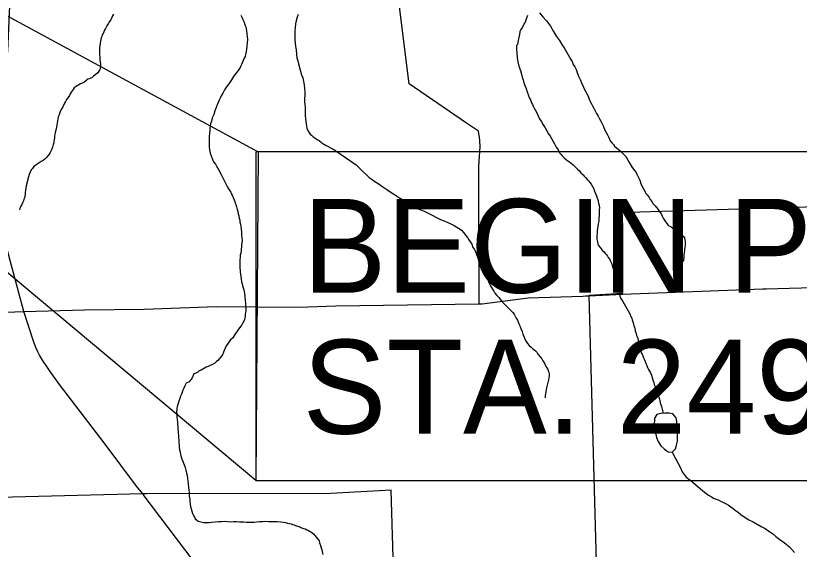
# Model space of a CAD drawing. Extents: x 0 to 44.3, y 0 to 22.
# Drawn here: x 6.296 to 7.465, y 15.453 to 16.249 of the extents above; entities that cross this region are included whole.
import ezdxf

# ---------------------------------------------------------------- set-up
doc = ezdxf.new("R2010")
doc.units = 0
for name, color, linetype in [('GM_X_City_Street', 7, 'Continuous'), ('GM_X_Corporation', 7, 'Continuous'), ('GM_X_County_Road', 7, 'Continuous'), ('GM_X_Minor_Lake', 7, 'Continuous'), ('GM_X_Minor_River', 7, 'Continuous'), ('SH_Text', 7, 'Continuous')]:
    doc.layers.add(name, color=color, linetype=linetype)

msp = doc.modelspace()

# ---------------------------------------------------------------- linework, layer by layer
at = {"layer": 'GM_X_City_Street'}
for points in [[(6.3085, 15.8078), (6.2524, 16.0154), (6.2644, 16.0723), (6.2847, 16.1957), (6.2898, 16.3085), (6.2909, 16.383), (6.3097, 16.5007), (6.3117, 16.6181), (6.3141, 16.71), (6.3024, 16.8069)], [(6.9874, 15.819), (6.9868, 16.0243), (6.9888, 16.0536), (6.9882, 16.062), (6.9879, 16.0675), (6.9871, 16.0729), (6.9862, 16.0764), (6.9684, 16.0883), (6.8829, 16.1469), (6.8664, 16.2823)]]:
    msp.add_lwpolyline(points, dxfattribs=at)
at = {"layer": 'GM_X_Corporation'}
for points in [[(7.7377, 15.9714), (7.1944, 15.955), (7.2008, 15.8343), (7.1511, 15.8316), (7.1669, 15.2531)], [(7.7377, 15.9714), (7.1944, 15.955), (7.2008, 15.8343), (7.1511, 15.8316), (7.1669, 15.2531)], [(6.8649, 15.2563), (6.8561, 15.5411), (6.7665, 15.5364), (6.4917, 15.5358), (6.4859, 15.5358), (6.1744, 15.5281), (6.1773, 15.2593)], [(6.8649, 15.2563), (6.8561, 15.5411), (6.7665, 15.5364), (6.4917, 15.5358), (6.4859, 15.5358), (6.1744, 15.5281), (6.1773, 15.2593)]]:
    msp.add_lwpolyline(points, dxfattribs=at)
at = {"layer": 'GM_X_County_Road'}
for points in [[(7.4152, 15.8417), (7.573, 15.8459), (7.9476, 15.8561), (8.0638, 15.86)], [(7.1459, 15.8309), (7.1509, 15.831), (7.2011, 15.8337), (7.4102, 15.8416), (7.4152, 15.8417)], [(5.4899, 15.7322), (5.7174, 15.7377), (5.884, 15.7402), (5.9198, 15.7511), (5.972, 15.7734), (6.0144, 15.7954), (6.0165, 15.7955), (6.0769, 15.7966), (6.0809, 15.7969), (6.2401, 15.8054), (6.3085, 15.8078), (6.399, 15.8104), (6.4879, 15.8111), (6.5954, 15.815), (6.7181, 15.8144), (6.7739, 15.816), (6.9874, 15.819), (6.992, 15.8191), (7.0603, 15.8282), (7.1419, 15.8307), (7.1459, 15.8309)], [(6.4858, 15.5357), (6.4766, 15.5475), (6.4298, 15.6097), (6.3617, 15.6991), (6.3476, 15.7181), (6.3426, 15.7258), (6.3365, 15.7352), (6.3319, 15.7426), (6.3292, 15.7476), (6.3266, 15.7539), (6.3231, 15.7637), (6.3085, 15.8078)], [(6.7741, 15.1514), (6.7729, 15.1531), (6.6991, 15.2503), (6.6354, 15.3379), (6.4864, 15.5349), (6.4858, 15.5357)]]:
    msp.add_lwpolyline(points, dxfattribs=at)
at = {"layer": 'GM_X_Minor_Lake'}
for points in [[(7.2833, 15.6248), (7.2833, 15.6314), (7.2824, 15.6435), (7.2813, 15.6492), (7.2763, 15.6552), (7.2706, 15.6563), (7.2642, 15.6559), (7.2581, 15.6555), (7.2525, 15.654), (7.2487, 15.6486), (7.2485, 15.6371)], [(7.2485, 15.6371), (7.2492, 15.6319), (7.2504, 15.6263), (7.2519, 15.6198), (7.2542, 15.6138), (7.2584, 15.6073), (7.2637, 15.6024), (7.2694, 15.5987), (7.2751, 15.5979)], [(7.2751, 15.5979), (7.2804, 15.6029), (7.2819, 15.6082), (7.283, 15.6143), (7.2833, 15.6204), (7.2833, 15.6248)]]:
    msp.add_lwpolyline(points, dxfattribs=at)
at = {"layer": 'GM_X_Minor_River'}
for points in [[(6.4424, 16.2511), (6.4409, 16.2484), (6.4395, 16.2458), (6.438, 16.2427), (6.4362, 16.24), (6.4343, 16.2365), (6.4325, 16.2335), (6.4303, 16.2296), (6.4288, 16.2269), (6.4277, 16.2247), (6.4266, 16.2223), (6.4255, 16.2201), (6.4248, 16.2178), (6.4237, 16.2155), (6.4234, 16.2132), (6.4227, 16.2105), (6.4223, 16.2078), (6.4216, 16.2044), (6.4213, 16.201), (6.4214, 16.1979), (6.4211, 16.1957), (6.4211, 16.193), (6.4211, 16.1907), (6.4216, 16.1869), (6.422, 16.1831), (6.4225, 16.1794), (6.4226, 16.1759), (6.4226, 16.1733), (6.4223, 16.1706), (6.4216, 16.1687), (6.419, 16.1637), (6.4168, 16.1622), (6.4126, 16.1587), (6.4097, 16.1563), (6.4059, 16.1547), (6.404, 16.1539), (6.4006, 16.1512), (6.398, 16.1493), (6.3946, 16.1477), (6.3928, 16.1469), (6.3867, 16.1434), (6.3837, 16.1414), (6.3819, 16.1387), (6.3808, 16.1368), (6.3793, 16.1345), (6.3778, 16.1322), (6.3764, 16.1295), (6.3742, 16.1264), (6.3723, 16.1237), (6.3705, 16.121), (6.369, 16.1184), (6.3668, 16.113), (6.3642, 16.1088), (6.3624, 16.1046), (6.361, 16.1011), (6.3599, 16.0977), (6.3592, 16.095), (6.3585, 16.092), (6.3582, 16.0889), (6.3575, 16.0859), (6.3572, 16.0824), (6.3561, 16.0779), (6.3554, 16.0748), (6.3547, 16.0714), (6.3544, 16.0695), (6.3544, 16.0672), (6.3537, 16.0638), (6.3534, 16.0619), (6.353, 16.0592), (6.3523, 16.0565), (6.3513, 16.0527), (6.3498, 16.0485), (6.3476, 16.045), (6.3461, 16.0424), (6.3443, 16.0397), (6.3421, 16.0373), (6.3398, 16.035), (6.3372, 16.0327), (6.3342, 16.0311), (6.3312, 16.0292), (6.3286, 16.0276), (6.326, 16.0256), (6.3233, 16.0237), (6.3215, 16.021), (6.3196, 16.0187), (6.3178, 16.0152), (6.3167, 16.0122), (6.3153, 16.0087), (6.3121, 15.995)], [(6.6322, 16.2497), (6.6338, 16.2463), (6.635, 16.2429), (6.6365, 16.2399), (6.6377, 16.2369), (6.6385, 16.2342), (6.6394, 16.232), (6.6402, 16.2293), (6.6406, 16.2263), (6.6411, 16.2218), (6.6415, 16.2176), (6.642, 16.213), (6.6413, 16.2081), (6.641, 16.2035), (6.6404, 16.1989), (6.64, 16.1951), (6.639, 16.1909), (6.6383, 16.1879), (6.6368, 16.1852), (6.6332, 16.176), (6.6321, 16.1741), (6.631, 16.1714), (6.6292, 16.1684), (6.6266, 16.1649), (6.6236, 16.1614), (6.621, 16.158), (6.6181, 16.153), (6.614, 16.1472), (6.6107, 16.1426), (6.6077, 16.138), (6.6052, 16.133), (6.6026, 16.1291), (6.6011, 16.1257), (6.5997, 16.1226), (6.5982, 16.1192), (6.5968, 16.1157), (6.5953, 16.1119), (6.5935, 16.1069), (6.5917, 16.1012), (6.5895, 16.0962), (6.5881, 16.0913), (6.587, 16.0874), (6.586, 16.0817), (6.5857, 16.0772), (6.5854, 16.0734), (6.5847, 16.0684), (6.5848, 16.0635), (6.5849, 16.0589), (6.585, 16.0536), (6.5855, 16.0483), (6.5863, 16.0437), (6.5876, 16.0396), (6.5895, 16.0358), (6.5915, 16.0309), (6.5943, 16.0272), (6.5962, 16.0234), (6.5986, 16.0193), (6.6029, 16.0122), (6.6068, 16.0042), (6.6088, 16.0001), (6.6124, 15.993), (6.6135, 15.9907), (6.6155, 15.9877), (6.617, 15.9854), (6.6178, 15.9836), (6.619, 15.9809)], [(6.7176, 16.2505), (6.7161, 16.2463), (6.7147, 16.241), (6.7137, 16.2364), (6.713, 16.2311), (6.7127, 16.2261), (6.7124, 16.2219), (6.7125, 16.2174), (6.7126, 16.2128), (6.713, 16.2083), (6.7135, 16.2026), (6.7144, 16.1977), (6.7149, 16.1916), (6.7157, 16.1859), (6.717, 16.1814), (6.7182, 16.1768), (6.7194, 16.1715), (6.7211, 16.1659), (6.7227, 16.1606), (6.7243, 16.1561), (6.7255, 16.1508), (6.7264, 16.1458), (6.7272, 16.1398), (6.7273, 16.1356), (6.7274, 16.1318), (6.7272, 16.1235), (6.7272, 16.1197), (6.7273, 16.1162), (6.7278, 16.1124), (6.7278, 16.1083), (6.7279, 16.1045), (6.728, 16.1003), (6.7285, 16.0946), (6.7298, 16.084), (6.7306, 16.081), (6.7318, 16.0776), (6.7334, 16.0749), (6.7353, 16.0723), (6.7376, 16.0705), (6.74, 16.0682), (6.7423, 16.0664), (6.7446, 16.0653), (6.7469, 16.0638), (6.7488, 16.0627), (6.7523, 16.0597), (6.755, 16.0575), (6.7722, 16.0483), (6.7569, 16.0564), (6.7573, 16.0564)], [(7.0593, 16.2492), (7.0579, 16.245), (7.0572, 16.2423), (7.0561, 16.2392), (7.0546, 16.2369), (7.052, 16.2316), (7.0498, 16.2281), (7.0483, 16.2251), (7.0476, 16.2209), (7.0462, 16.2144), (7.0445, 16.206), (7.043, 16.2041), (7.0431, 16.1995), (7.0435, 16.1934), (7.044, 16.1858), (7.0449, 16.1801), (7.0465, 16.1737), (7.0489, 16.1669), (7.0505, 16.1616), (7.0517, 16.157), (7.0529, 16.1533), (7.0542, 16.1487), (7.0561, 16.1438), (7.0573, 16.14), (7.0589, 16.1351), (7.0605, 16.1313), (7.0617, 16.1283), (7.0629, 16.1249), (7.0645, 16.1222), (7.0657, 16.1188), (7.0672, 16.1162), (7.068, 16.1139), (7.0692, 16.1117), (7.0708, 16.1083), (7.0731, 16.1049), (7.0751, 16.1003), (7.0774, 16.0951), (7.0806, 16.0905), (7.0829, 16.086), (7.0857, 16.0815), (7.0884, 16.077), (7.0907, 16.0728), (7.0931, 16.0691), (7.0997, 16.0577), (7.1009, 16.0555), (7.1025, 16.0528), (7.104, 16.0502), (7.1056, 16.0476), (7.1072, 16.0445), (7.1095, 16.0419), (7.1114, 16.0397), (7.1141, 16.037), (7.1176, 16.0337), (7.121, 16.0314), (7.1241, 16.0292), (7.1276, 16.0262), (7.1307, 16.0232), (7.1342, 16.0198), (7.1369, 16.0172)], [(7.0775, 16.2529), (7.0825, 16.2472), (7.0876, 16.2412), (7.0938, 16.233), (7.0981, 16.2254), (7.1028, 16.2179), (7.1071, 16.2115), (7.1106, 16.2058), (7.1141, 16.2006), (7.1219, 16.187), (7.1243, 16.1832), (7.1262, 16.1802), (7.1278, 16.176), (7.1301, 16.1723), (7.1321, 16.1685), (7.1337, 16.164), (7.1357, 16.1587), (7.138, 16.1534), (7.1404, 16.1477), (7.1428, 16.1424), (7.1447, 16.1386), (7.1463, 16.1352), (7.1479, 16.1322), (7.1499, 16.1285), (7.1522, 16.1228), (7.1546, 16.1183), (7.1565, 16.1145), (7.1585, 16.1107), (7.1605, 16.1069), (7.1624, 16.1028), (7.1648, 16.099), (7.1671, 16.0952), (7.1691, 16.0915), (7.171, 16.0877), (7.173, 16.0835), (7.1746, 16.0782), (7.177, 16.0745), (7.1789, 16.0711), (7.1809, 16.0669), (7.1829, 16.0624), (7.1852, 16.059), (7.1875, 16.0568), (7.1894, 16.0541), (7.1921, 16.0519), (7.1945, 16.0496), (7.1975, 16.0474), (7.2006, 16.0444), (7.206, 16.0388), (7.2107, 16.0309), (7.2158, 16.0226), (7.2197, 16.0173), (7.2216, 16.0147), (7.2224, 16.0124), (7.224, 16.0094), (7.2248, 16.0075), (7.2268, 16.0033), (7.2287, 15.998), (7.2366, 15.9833), (7.2381, 15.9815), (7.2409, 15.9777), (7.2424, 15.9747), (7.2448, 15.9717), (7.2471, 15.9683), (7.2498, 15.9653), (7.2521, 15.9626), (7.2544, 15.96), (7.256, 15.9574), (7.2576, 15.9547), (7.2591, 15.9521), (7.2603, 15.9498), (7.2619, 15.9468), (7.2638, 15.9438), (7.2654, 15.9412), (7.2677, 15.9382), (7.2693, 15.9359), (7.2716, 15.9348), (7.2739, 15.9337), (7.277, 15.9315), (7.2789, 15.9303), (7.2812, 15.9289), (7.2831, 15.9277), (7.2854, 15.9255), (7.2873, 15.9236), (7.2896, 15.9221), (7.2916, 15.9199), (7.2935, 15.9173), (7.2943, 15.9142), (7.2948, 15.9119), (7.2948, 15.907), (7.2941, 15.9032), (7.2938, 15.9005), (7.2935, 15.8986), (7.2931, 15.8959), (7.2928, 15.8921), (7.2925, 15.8876), (7.2918, 15.8822)], [(6.7722, 16.0483), (6.8039, 16.0264), (6.8093, 16.0211), (6.8143, 16.0159), (6.8193, 16.0114), (6.8235, 16.0077), (6.8278, 16.0047), (6.832, 16.0017), (6.837, 15.9983), (6.8439, 15.9935), (6.8497, 15.9894), (6.8562, 15.9853), (6.8627, 15.9809), (6.8685, 15.9771), (6.8842, 15.9682), (6.8881, 15.9656), (6.8915, 15.9638), (6.8942, 15.9623), (6.8977, 15.9605), (6.9022, 15.9586), (6.9065, 15.9568), (6.9114, 15.9542), (6.9172, 15.9512), (6.9237, 15.9479), (6.9298, 15.945), (6.936, 15.9424), (6.9405, 15.9406), (6.9444, 15.9391), (6.9474, 15.9372), (6.9501, 15.9358), (6.954, 15.9335), (6.9566, 15.932), (6.9589, 15.9306), (6.9612, 15.9291), (6.9647, 15.9249), (6.9671, 15.9216), (6.9698, 15.9182), (6.9721, 15.9148), (6.9741, 15.9114), (6.9764, 15.908), (6.9776, 15.9042), (6.9799, 15.9008), (6.9819, 15.8971), (6.9835, 15.8929), (6.9851, 15.8887), (6.9871, 15.8842), (6.989, 15.8789), (6.9918, 15.8736), (6.9945, 15.8687), (6.9973, 15.8642), (6.9992, 15.8593), (7.0005, 15.8551), (7.002, 15.851), (7.0032, 15.8483), (7.0044, 15.8461), (7.0056, 15.8434), (7.0071, 15.8411), (7.0091, 15.8381), (7.011, 15.8351), (7.0138, 15.8317), (7.0169, 15.8284), (7.0203, 15.8242), (7.0242, 15.8197), (7.0354, 15.8089), (7.0377, 15.8062), (7.0397, 15.8036), (7.0413, 15.8006), (7.0428, 15.7976), (7.0444, 15.7949), (7.0456, 15.7923), (7.0468, 15.7893), (7.0483, 15.7862), (7.0495, 15.7825), (7.0515, 15.7779), (7.0527, 15.7738), (7.0547, 15.7692), (7.0567, 15.7643), (7.0594, 15.7602), (7.0621, 15.7572), (7.0648, 15.7545), (7.0671, 15.7527), (7.069, 15.7512), (7.0713, 15.7493), (7.0733, 15.7471), (7.0756, 15.7437), (7.0783, 15.7403), (7.0807, 15.7373), (7.0826, 15.7343), (7.0842, 15.7316), (7.0858, 15.7282), (7.0869, 15.7256), (7.0885, 15.7237), (7.09, 15.7211), (7.0905, 15.7192), (7.0913, 15.7173), (7.0917, 15.7142)], [(7.1369, 16.0172), (7.1392, 16.0146), (7.1423, 16.0116), (7.1442, 16.0097), (7.1461, 16.0075), (7.1492, 16.0041), (7.1508, 16.0018), (7.1527, 16), (7.1543, 15.9977), (7.1566, 15.9943), (7.1582, 15.9905), (7.1594, 15.9871), (7.161, 15.9834), (7.1622, 15.98), (7.1634, 15.9769), (7.1642, 15.9747), (7.165, 15.972), (7.1654, 15.9686), (7.1662, 15.9663), (7.1667, 15.9618), (7.1663, 15.9599), (7.1664, 15.9561), (7.1664, 15.9519), (7.1661, 15.9465), (7.1658, 15.9424), (7.1651, 15.9382), (7.1644, 15.9347), (7.1637, 15.9309), (7.1634, 15.9279), (7.1628, 15.918), (7.1628, 15.9157), (7.1637, 15.9115), (7.1645, 15.9081), (7.1653, 15.9062), (7.1672, 15.9036), (7.1699, 15.9006), (7.1715, 15.8983), (7.1738, 15.8965), (7.1754, 15.8942), (7.1773, 15.8923), (7.1788, 15.8901), (7.18, 15.8882), (7.1823, 15.8852), (7.1835, 15.8829), (7.1843, 15.881), (7.1851, 15.8788), (7.1863, 15.8742), (7.1871, 15.8719), (7.1883, 15.8682), (7.1899, 15.864), (7.1916, 15.8564), (7.1944, 15.8454), (7.1964, 15.8413), (7.1964, 15.8375), (7.1965, 15.8356), (7.1965, 15.8329), (7.1977, 15.8284), (7.1997, 15.8257), (7.2016, 15.8227), (7.2036, 15.819), (7.2114, 15.805), (7.2126, 15.8027), (7.2134, 15.8008), (7.2149, 15.7974), (7.2154, 15.7952), (7.2165, 15.7921), (7.2174, 15.7895), (7.2182, 15.7865), (7.2194, 15.7831), (7.2202, 15.7789), (7.2214, 15.7751), (7.2222, 15.7721), (7.223, 15.7698), (7.2238, 15.7675), (7.2246, 15.7649), (7.225, 15.7622), (7.2258, 15.7596), (7.2263, 15.7565), (7.2271, 15.7535), (7.2279, 15.7512), (7.2283, 15.7494), (7.2291, 15.7463), (7.2306, 15.7441), (7.2314, 15.7418), (7.2326, 15.7384), (7.2338, 15.7357), (7.235, 15.7331), (7.2362, 15.7301), (7.2374, 15.7274), (7.2386, 15.7244), (7.2398, 15.7214), (7.2413, 15.7187), (7.2429, 15.7161), (7.2445, 15.7127), (7.2456, 15.7093), (7.2465, 15.7059), (7.2477, 15.7021), (7.2485, 15.6987), (7.2497, 15.6957), (7.2505, 15.693), (7.2517, 15.69)], [(6.3121, 15.995), (6.3114, 15.9916), (6.3111, 15.9882), (6.3104, 15.9851), (6.3105, 15.9821), (6.3101, 15.9798), (6.3094, 15.9771), (6.3087, 15.9752), (6.308, 15.9725), (6.3065, 15.9695), (6.3051, 15.9664), (6.3036, 15.9637), (6.3025, 15.9614), (6.3022, 15.9591), (6.3018, 15.9591), (6.3022, 15.9591)], [(6.619, 15.9809), (6.6222, 15.9741), (6.623, 15.9719), (6.6238, 15.9692), (6.6246, 15.967), (6.6254, 15.9639), (6.6266, 15.9598), (6.6275, 15.9568), (6.6283, 15.9534), (6.6291, 15.9503), (6.6295, 15.9469), (6.6304, 15.9439), (6.6308, 15.9409), (6.6316, 15.9379), (6.632, 15.9344), (6.6325, 15.9307), (6.633, 15.9261), (6.633, 15.9223), (6.6335, 15.9174), (6.634, 15.9136), (6.6336, 15.9102), (6.6333, 15.9067), (6.633, 15.9037), (6.6327, 15.901), (6.6324, 15.898), (6.632, 15.8949), (6.6313, 15.8915), (6.631, 15.8881), (6.6307, 15.885), (6.6304, 15.8812), (6.6305, 15.8782), (6.6305, 15.8752), (6.6306, 15.8718), (6.631, 15.8691), (6.6311, 15.8664), (6.6315, 15.8634), (6.6319, 15.86), (6.6324, 15.8562), (6.6332, 15.852), (6.634, 15.849), (6.6348, 15.8464), (6.6357, 15.843), (6.6365, 15.84), (6.6369, 15.8377), (6.6373, 15.8347), (6.6378, 15.8312), (6.6382, 15.8282), (6.6387, 15.8252), (6.6387, 15.8229), (6.6391, 15.821), (6.6392, 15.8187), (6.6393, 15.8127), (6.6393, 15.8108), (6.6394, 15.8085), (6.639, 15.8062), (6.6387, 15.8043), (6.6383, 15.802), (6.6384, 15.8001), (6.638, 15.7982), (6.6377, 15.7959), (6.6366, 15.7932), (6.6348, 15.7898), (6.6337, 15.7879), (6.6322, 15.7856), (6.6303, 15.7836), (6.6278, 15.7798), (6.6255, 15.7767), (6.6229, 15.7732), (6.62, 15.7686), (6.6166, 15.7655), (6.6144, 15.7621), (6.6122, 15.759), (6.6104, 15.7563), (6.6089, 15.7532), (6.6071, 15.7498), (6.606, 15.7471), (6.6045, 15.7433), (6.6027, 15.7406), (6.6008, 15.7379), (6.5979, 15.7348), (6.596, 15.7332), (6.5934, 15.7309), (6.5896, 15.7286), (6.5862, 15.727), (6.5832, 15.7258), (6.5806, 15.7246), (6.578, 15.723), (6.5753, 15.7218), (6.5731, 15.7203), (6.5701, 15.7191), (6.5678, 15.7175), (6.5648, 15.7156), (6.5622, 15.7148), (6.5593, 15.7086), (6.5548, 15.7029), (6.5507, 15.7009), (6.5496, 15.699), (6.5485, 15.6967), (6.547, 15.6932), (6.5456, 15.6905), (6.5445, 15.6875)], [(7.0917, 15.7142), (7.0917, 15.7116), (7.0914, 15.7089), (7.0907, 15.7059), (7.09, 15.7021), (7.0889, 15.6979), (7.0878, 15.694), (7.0871, 15.691), (7.0868, 15.6879), (7.0865, 15.6853), (7.0858, 15.6822), (7.0858, 15.6796), (7.0854, 15.6784)], [(6.5445, 15.6875), (6.5434, 15.6844), (6.5423, 15.6814), (6.5412, 15.6779), (6.5398, 15.6741), (6.5369, 15.6657), (6.5366, 15.6634), (6.5366, 15.6607), (6.5363, 15.6581), (6.5364, 15.655), (6.5364, 15.6509), (6.5369, 15.6467), (6.5374, 15.6429), (6.5378, 15.6395), (6.5379, 15.6361), (6.5383, 15.6319), (6.5384, 15.6292), (6.5388, 15.6262), (6.5389, 15.6232), (6.5393, 15.6198), (6.5394, 15.616), (6.5394, 15.6122), (6.5399, 15.6084), (6.5403, 15.605), (6.5408, 15.6016), (6.5416, 15.5982), (6.542, 15.5951), (6.5433, 15.5906), (6.5445, 15.5868), (6.5461, 15.5831), (6.5477, 15.5793), (6.5489, 15.5751), (6.5501, 15.571), (6.5509, 15.5668), (6.5518, 15.563), (6.5526, 15.5589), (6.5531, 15.5547), (6.5535, 15.5509), (6.554, 15.5456), (6.5544, 15.5414), (6.5549, 15.5373), (6.555, 15.5335), (6.5554, 15.5301), (6.5558, 15.5274), (6.5559, 15.5244), (6.5567, 15.5206), (6.5572, 15.5168), (6.558, 15.5134), (6.5588, 15.51), (6.56, 15.5066), (6.5616, 15.5036), (6.5628, 15.5009), (6.564, 15.4987), (6.5659, 15.4972), (6.5682, 15.4953), (6.5762, 15.4932), (6.5785, 15.4929), (6.5815, 15.4929), (6.585, 15.493), (6.5884, 15.4934), (6.594, 15.4943), (6.5986, 15.4948), (6.6031, 15.4948), (6.6073, 15.4949), (6.6119, 15.4946), (6.6164, 15.4943), (6.621, 15.4944), (6.6255, 15.4945), (6.6301, 15.4942), (6.6335, 15.4939), (6.6366, 15.4939), (6.6407, 15.4936), (6.6449, 15.4937), (6.6479, 15.4934), (6.6517, 15.4938), (6.6555, 15.4939), (6.6601, 15.4944), (6.665, 15.4945), (6.6695, 15.4949), (6.6734, 15.4946), (6.6775, 15.4947), (6.6817, 15.4944), (6.6863, 15.4945), (6.6916, 15.4942), (6.6954, 15.4935), (6.6988, 15.4932), (6.7015, 15.4921), (6.7045, 15.4914), (6.7072, 15.4911), (6.7091, 15.4903), (6.7114, 15.4896), (6.7137, 15.4889), (6.7164, 15.4878), (6.7187, 15.4871), (6.7225, 15.4853), (6.7255, 15.4842), (6.7282, 15.4835), (6.7305, 15.4824), (6.7324, 15.4817), (6.7347, 15.4802), (6.7366, 15.4791)], [(7.2517, 15.69), (7.2525, 15.6873), (7.2536, 15.6855), (7.2544, 15.6824), (7.2553, 15.6798), (7.2561, 15.6771), (7.2569, 15.6749), (7.2573, 15.6714), (7.2593, 15.6662), (7.2597, 15.6643), (7.2605, 15.662), (7.2609, 15.6601), (7.2613, 15.6582), (7.2617, 15.6555)], [(7.2751, 15.5979), (7.2882, 15.5734), (7.2878, 15.5745), (7.2901, 15.5685), (7.2929, 15.5647), (7.2963, 15.5606), (7.3014, 15.5565), (7.3064, 15.5528), (7.321, 15.5404), (7.3256, 15.5371), (7.3295, 15.5341), (7.3337, 15.5315), (7.3379, 15.5289), (7.3436, 15.5271), (7.3475, 15.5249), (7.3517, 15.523), (7.3555, 15.5208), (7.359, 15.5189), (7.3628, 15.5167), (7.3663, 15.5141), (7.3697, 15.5111), (7.3736, 15.5085), (7.3778, 15.5051), (7.3824, 15.5018), (7.3897, 15.4973), (7.3958, 15.494), (7.402, 15.4907), (7.4081, 15.4873), (7.4139, 15.484), (7.4193, 15.4803), (7.4246, 15.4766), (7.43, 15.4725), (7.4358, 15.468), (7.4427, 15.4628), (7.45, 15.4568), (7.4578, 15.4485)], [(6.7366, 15.4791), (6.7386, 15.4776), (6.7405, 15.4761), (6.742, 15.4742), (6.7475, 15.4679), (6.7487, 15.4656), (6.7495, 15.4626), (6.7507, 15.4588), (6.7519, 15.4554), (6.7527, 15.4524), (6.7535, 15.4498), (6.7539, 15.4475), (6.7544, 15.4456), (6.7544, 15.4452)]]:
    msp.add_lwpolyline(points, dxfattribs=at)
at = {"layer": 'SH_Text'}
for points in [[(6.6542, 15.5556), (4.9858, 16.9516), (6.6579, 16.0456)], [(6.6542, 15.5556), (8.3897, 15.5556), (8.3897, 16.0456), (6.6542, 16.0456)]]:
    msp.add_lwpolyline(points, close=True, dxfattribs=at)

# ---------------------------------------------------------------- texts
for s, p in [('BEGIN PROJECT', (6.7242, 15.8356)), ('STA. 249+35.79', (6.7242, 15.6256))]:
    msp.add_text(s, height=0.14, dxfattribs=at).set_placement(p)

doc.saveas('drawing.dxf')
